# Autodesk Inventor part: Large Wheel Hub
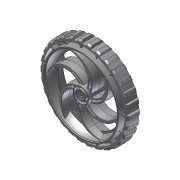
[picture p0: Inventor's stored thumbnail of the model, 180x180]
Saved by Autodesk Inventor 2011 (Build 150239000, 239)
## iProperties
Created: 2010-06
Part Number: Large Wheel Hub
Document SubType Name: Modeling
Designer: kurdi
Density: 1 g/cm^3
Author: kurdi
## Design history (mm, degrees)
workplane "Work Plane1"
sketch "Sketch2"
  geometry: L1 (10.567, 12.411)-(11, 0); L2 (9.792, 12.7)-(10.316, 12.7); L3 (9.314, 9)-(9.433, 12.411); L4 (6.686, 9)-(9.314, 9); L5 (6.567, 12.406)-(6.686, 9); L6 (5.978, 12.7)-(6.262, 12.7); L7 (42.845, 0.75)-(44.637, 0.75); L8 (42.779, 0)-(42.845, 0.75); L9 (57, 8.5)-(57, 0); L10 (55, 8.5)-(57, 8.5); L11 (54.869, 1)-(55, 8.5); L12 (50.838, 1)-(54.869, 1); L13 (50.639, 12.401)-(50.838, 1); L14 (49.42, 12.7)-(50.334, 12.7); L15 (48.362, 11.769)-(49.204, 12.611); L16 (0, 0)-(57, 0); L17 (0, 12.125)-(0, 0); L18 (0, 46.6)-(0, 0); L19 (10.567, -12.411)-(11, 0); L20 (9.792, -12.7)-(10.316, -12.7); L21 (9.314, -9)-(9.433, -12.411); L22 (6.686, -9)-(9.314, -9); L23 (50.838, -1)-(54.869, -1); L24 (54.869, -1)-(55, -8.5); L25 (57, -8.5)-(57, 0); L26 (0, -12.125)-(0, 0); L27 (42.779, 0)-(42.845, -0.75); L28 (42.845, -0.75)-(44.637, -0.75); L29 (48.362, -11.769)-(49.204, -12.611); L30 (49.42, -12.7)-(50.334, -12.7); L31 (50.639, -12.401)-(50.838, -1); L32 (55, -8.5)-(57, -8.5); L33 (5.978, 12.7)-(5.978, 12.446); L34 (5.978, 12.446)-(5.914, 12.446); L35 (5.914, 12.446)-(5.914, 12.7); L36 (5.914, 12.7)-(5.445, 12.7); L37 (5.978, -12.7)-(6.262, -12.7); L38 (5.978, -12.446)-(5.914, -12.446); L39 (5.978, -12.7)-(5.978, -12.446); L40 (5.914, -12.446)-(5.914, -12.7); L41 (5.914, -12.7)-(5.445, -12.7); L42 (6.567, -12.406)-(6.686, -9); A1 r 0.305 centre (10.262, 12.4) between (10.567, 12.411) and (10.316, 12.7); A2 r 0.305 centre (9.738, 12.4) between (9.792, 12.7) and (9.433, 12.411); A3 r 0.305 centre (6.262, 12.395) between (6.567, 12.406) and (6.262, 12.7); A4 r 25.019 centre (0.079, 37.144) between (0, 12.125) and (5.381, 12.693); A5 r 22 centre (26.3, 12.649) between (44.895, 0.892) and (48.274, 11.569); A6 r 0.305 centre (44.637, 1.055) between (44.637, 0.75) and (44.895, 0.892); A7 r 0.305 centre (50.334, 12.395) between (50.639, 12.401) and (50.334, 12.7); A8 r 0.305 centre (49.42, 12.395) between (49.42, 12.7) and (49.204, 12.611); A9 r 0.305 centre (48.578, 11.554) between (48.362, 11.769) and (48.274, 11.569); A10 r 0.305 centre (10.262, -12.4) between (10.316, -12.7) and (10.567, -12.411); A11 r 0.305 centre (9.738, -12.4) between (9.433, -12.411) and (9.792, -12.7); A12 r 0.305 centre (44.637, -1.055) between (44.895, -0.892) and (44.637, -0.75); A13 r 0.305 centre (48.578, -11.554) between (48.274, -11.569) and (48.362, -11.769); A14 r 0.305 centre (49.42, -12.395) between (49.204, -12.611) and (49.42, -12.7); A15 r 22 centre (26.3, -12.649) between (48.274, -11.569) and (44.895, -0.892); A16 r 0.305 centre (50.334, -12.395) between (50.334, -12.7) and (50.639, -12.401); A17 r 0.305 centre (5.445, 12.395) between (5.445, 12.7) and (5.381, 12.693); A18 r 0.305 centre (6.262, -12.395) between (6.262, -12.7) and (6.567, -12.406); A19 r 0.305 centre (5.445, -12.395) between (5.381, -12.693) and (5.445, -12.7); A20 r 25.019 centre (0.079, -37.144) between (5.381, -12.693) and (0, -12.125); 10 further points
  constraints: 86 end point, 44 point on circle, 42 symmetric about line, 20 centre point, 15 tangent, 11 point on line, 5 horizontal, 5 perpendicular, 3 parallel, 2 collinear, 2 vertical, 1 horizontal alignment, 10 other
  dimensions: "d0" = 22 radius of A5; "d14" = 0.3048 radius of A8; "d15" = 0.3048 radius of A7; "d16" = 25.019 radius of A4; "d18" = 0.3048 radius of A2; "d19" = 0.3048 radius of A1; "d21" = 12.4 distance from line of L16 A2.centre; "d24" = 11 distance from line of L1.end L18; "d27" = 2.13091 distance from line of L9 L11.start; "d28" = 4.03112 distance of L12.start L11.start; "d29" = 8.5 distance of L9.start L9.end; "d30" = 2 distance of L10.start L9.start; "d31" = 1 distance between parallel lines of L16 L12; "d32" = 0.3048 radius of A6; "d36" = 2.62857 distance of L4.start L3.start; "d37" = 9 distance between parallel lines of L16 L4; "d38" = 6.68571 distance from line of L17 L4.start; "d42" = 12.64919 distance from line of L16 A5.centre; "d43" = 26.30006 distance from line of L18 A5.centre; "d44" = 0.3048 radius of A9; "d45" = 0.91468 distance of L14.start L14.end; "d46" = 12.7 distance between parallel lines of L16 L14; "d47" = 0.75 distance between parallel lines of L16 L7; "d48" = 0.999943 deg angle of L13 L9; "d49" = 45 deg angle of L9 L15; "d52" = 8.5 distance from line of point (0, 0) L10; "d55" = 38.1 distance from line of L18.start L10; "d60" = 57 distance between parallel lines of L18 L9; "d61" = 57 distance from line of point (0, 0) L9; "d64" = 14.22098 distance from line of L25 L8.start; "d67" = 0.0635 distance of L33.end L34.end; "d69" = 0.254 distance of L6.start L33.end; "d70" = 0.3048 radius of A3; "d71" = 0.3048 radius of A17; "d73" = 51.02237 distance between parallel lines of L33 L9; "d74" = 4.2 distance between parallel lines of L37 L32; "d76" = 51.5546 distance from line of L36.end L9; "d77" = 51.58737 distance from line of point (5.413, 12.7) L9; "d78" = 92 deg angle of L4 L5; "d123" = 92 deg angle of L4 L3; "d130" = 95 deg angle of L16 L8; "d131" = 13.87606 distance from line of point (43.124, 0.75) L9; "d132" = 14.1797 distance from line of point (42.82, 0.472) L9
revolve "Revolution1" sketch "Sketch2" stored, may be unused: angle "d66" = 90 deg
sketch "Sketch3"
  geometry: L1 (1.612, 0.952)-(1.558, 1.007); L2 (1.558, 1.025)-(1.612, 1.079); L3 (1.612, 1.104)-(1.612, 1.079); L4 (1.558, 1.177)-(1.612, 1.231); L5 (1.612, 1.362)-(1.612, 1.231); L6 (1.232, 1.612)-(1.177, 1.558); L7 (1.159, 1.558)-(1.105, 1.612); L8 (1.079, 1.612)-(1.105, 1.612); L9 (1.232, 1.612)-(1.362, 1.612); L10 (1.612, 0.952)-(1.612, -0.952); L11 (1.558, -1.007)-(1.612, -0.952); L12 (1.612, 1.104)-(1.558, 1.159); L13 (1.079, 1.612)-(1.025, 1.558); L14 (-1.362, 1.612)-(-1.231, 1.612); L15 (-1.177, 1.558)-(-1.231, 1.612); L16 (1.007, 1.558)-(0.952, 1.612); L17 (-0.952, 1.613)-(0.952, 1.612); L18 (-0.952, 1.613)-(-1.007, 1.558); L19 (-1.024, 1.558)-(-1.079, 1.612); L20 (-1.104, 1.613)-(-1.079, 1.612); L21 (-1.104, 1.613)-(-1.159, 1.558); L22 (1.613, -1.079)-(1.558, -1.024); L23 (1.613, -1.079)-(1.612, -1.105); L24 (1.558, -1.159)-(1.612, -1.105); L25 (1.613, -1.231)-(1.558, -1.177); L26 (1.613, -1.231)-(1.612, -1.362); L27 (1.362, -1.612)-(1.231, -1.612); L28 (1.177, -1.558)-(1.231, -1.612); L29 (1.104, -1.613)-(1.079, -1.612); L30 (1.024, -1.558)-(1.079, -1.612); L31 (0.952, -1.613)-(1.007, -1.558); L32 (0.952, -1.613)-(-0.952, -1.612); L33 (1.104, -1.613)-(1.159, -1.558); L34 (-1.007, -1.558)-(-0.952, -1.612); L35 (-1.079, -1.612)-(-1.025, -1.558); L36 (-1.079, -1.612)-(-1.105, -1.612); L37 (-1.159, -1.558)-(-1.105, -1.612); L38 (-1.232, -1.612)-(-1.177, -1.558); L39 (-1.612, -0.952)-(-1.558, -1.007); L40 (-1.558, -1.025)-(-1.612, -1.079); L41 (-1.612, -1.104)-(-1.612, -1.079); L42 (-1.612, -1.104)-(-1.558, -1.159); L43 (-1.558, -1.177)-(-1.612, -1.231); L44 (-1.612, -1.362)-(-1.612, -1.231); L45 (-1.232, -1.612)-(-1.362, -1.612); L46 (-1.612, -0.952)-(-1.612, 0.952); L47 (-1.558, 1.007)-(-1.612, 0.952); L48 (-1.613, 1.079)-(-1.558, 1.024); L49 (-1.613, 1.079)-(-1.612, 1.105); L50 (-1.558, 1.159)-(-1.612, 1.105); L51 (-1.613, 1.231)-(-1.558, 1.177); L52 (-1.613, 1.231)-(-1.612, 1.362); A1 r 0.013 centre (1.567, 1.016) between (1.558, 1.025) and (1.558, 1.007); A2 r 0.013 centre (1.567, 1.168) between (1.558, 1.177) and (1.558, 1.159); A3 r 0.25 centre (1.362, 1.362) between (1.612, 1.362) and (1.362, 1.612); A4 r 0.013 centre (1.168, 1.567) between (1.159, 1.558) and (1.177, 1.558); A5 r 0.012 centre (-1.016, 1.566) between (-1.024, 1.558) and (-1.007, 1.558); A6 r 0.012 centre (-1.168, 1.566) between (-1.177, 1.558) and (-1.159, 1.558); A7 r 0.013 centre (1.016, 1.567) between (1.007, 1.558) and (1.025, 1.558); A8 r 0.012 centre (1.566, -1.016) between (1.558, -1.007) and (1.558, -1.024); A9 r 0.013 centre (1.567, -1.168) between (1.558, -1.159) and (1.558, -1.177); A10 r 0.25 centre (1.362, -1.362) between (1.362, -1.612) and (1.612, -1.362); A11 r 0.012 centre (1.168, -1.566) between (1.177, -1.558) and (1.159, -1.558); A12 r 0.012 centre (1.016, -1.566) between (1.024, -1.558) and (1.007, -1.558); A13 r 0.013 centre (-1.016, -1.567) between (-1.007, -1.558) and (-1.025, -1.558); A14 r 0.013 centre (-1.168, -1.567) between (-1.159, -1.558) and (-1.177, -1.558); A15 r 0.013 centre (-1.567, -1.168) between (-1.558, -1.177) and (-1.558, -1.159); A16 r 0.013 centre (-1.567, -1.016) between (-1.558, -1.025) and (-1.558, -1.007); A17 r 0.25 centre (-1.362, -1.362) between (-1.612, -1.362) and (-1.362, -1.612); A18 r 0.25 centre (-1.362, 1.362) between (-1.362, 1.612) and (-1.612, 1.362); A19 r 0.013 centre (-1.567, 1.168) between (-1.558, 1.159) and (-1.558, 1.177); A20 r 0.012 centre (-1.566, 1.016) between (-1.558, 1.007) and (-1.558, 1.024); 1 further point
  constraints: 104 end point, 40 point on circle, 20 centre point
feature "iFeature1:1" sketch "Sketch3"
sketch "Sketch4"
  geometry: A1 r 26.527 centre (-14.987, 15.537) between (9.122, 4.473) and (-1.422, 38.333); A2 r 35.155 centre (-19.399, 8.122) between (-1.422, 38.333) and (-22.795, 43.113); A3 r 22.463 centre (-16.436, 17.645) between (4.368, 9.173) and (-5.564, 37.302); A4 r 37.313 centre (-23.624, 4.651) between (-5.564, 37.302) and (-24.882, 41.943); A5 r 24.749 centre (-14.987, 15.537) between (7.972, 6.298) and (8.602, 23.024); A6 r 24.241 centre (-16.436, 17.645) between (5.914, 8.261) and (7.277, 22.675); A7 r 0.686 centre (7.948, 22.817) between (8.602, 23.024) and (7.277, 22.675); A8 r 10.16 centre (0, 0) between (5.914, 8.261) and (4.368, 9.173); A9 r 10.16 centre (0, 0) between (9.122, 4.473) and (7.972, 6.298); A10 r 48.768 centre (0, 0) between (-22.795, 43.113) and (-24.882, 41.943); A11 r 10.16 centre (0, 0) between (7.972, 6.298) and (5.914, 8.261); 2 further points
  constraints: 22 point on circle, 11 centre point, 4 tangent, 3 coincident, 1 concentric
  dimensions: "d79" = 0.6858 radius of A7; "d85" = 26.52672 radius of A1; "d86" = 35.15477 radius of A2; "d87" = 37.31272 radius of A4; "d88" = 22.46313 radius of A3; "d89" = 48.768 radius of A10; "d90" = 1.778 radial gap between concentric circles of A1 A5; "d91" = 1.778 radial gap between concentric circles of A3 A6; "d92" = 10.16 radius of A9; "d93" = 10.16 radius of A8; "d103" = 16.43647 horizontal distance of A3.centre point (0, 0); "d104" = 19.39935 horizontal distance of A2.centre point (0, 0); "d105" = 23.62407 horizontal distance of A4.centre point (0, 0); "d106" = 4.65123 vertical distance of A4.centre point (0, 0); "d107" = 8.12226 vertical distance of point (0, 0) A2.centre; "d108" = 14.98711 horizontal distance of point (0, 0) A1.centre
extrude "Extrusion1" join sketch "Sketch4" distance "d110" = 8.9916; taper "d111" = 4 deg
extrude "Extrusion2" cut sketch "Sketch4" distance "d112" = 8.255; taper "d113" = -2 deg
sketch "Sketch6"
  geometry: C1 r 9.314 at (0, 0) reference; C2 r 6.686 at (0, 0) reference; A1 r 24.241 centre (-16.436, 17.645) between (6.118, 8.761) and (7.277, 22.675); A2 r 24.749 centre (-14.987, 15.537) between (8.192, 6.862) and (8.602, 23.024); A3 r 9.314 centre (0, 0) between (5.565, 7.469) and (7.59, 5.399); A4 r 6.686 centre (0, 0) between (4.312, 5.11) and (6.14, 2.646); A5 r 24.241 centre (-16.436, 17.645) between (4.312, 5.11) and (5.565, 7.469); A6 r 24.749 centre (-14.987, 15.537) between (6.14, 2.646) and (7.59, 5.399); A7 r 6.686 centre (0, 0) between (6.14, 2.646) and (4.312, 5.11); A8 r 9.314 centre (0, 0) between (7.59, 5.399) and (5.565, 7.469)
  constraints: 16 point on circle, 8 centre point, 6 concentric
extrude "Extrusion4" cut sketch "Sketch6" distance "d116" = 8.255; taper "d117" = -2 deg; dims "d118" = 2.54, "d119" = -2 deg
fillet "Fillet1" dims "d121" = 0.381
mirror "Mirror1"
sketch "Sketch7"
  geometry: L1 (3.523, 42.634)-(3.523, 43.142); L2 (1.43, 37.168)-(0.993, 36.908); A1 r 35.784 centre (-19.399, 8.122) between (-1.1, 38.873) and (-7.967, 42.031) reference; A2 r 42.779 centre (0, 0) between (-14.604, 40.209) and (-7.967, 42.031) reference; A3 r 42.779 centre (0, 0) between (3.523, 42.634) and (-7.967, 42.031); A4 r 3.048 centre (3.272, 39.596) between (3.523, 42.634) and (1.43, 37.168); A5 r 43.285 centre (0, 0) between (3.523, 43.142) and (-9.981, 42.119); A6 r 35.277 centre (-19.399, 8.122) between (0.993, 36.908) and (-9.981, 42.119); A7 r 27.155 centre (-14.987, 15.537) between (9.928, 4.736) and (-1.1, 38.873) reference; 1 further point
  constraints: 11 point on circle, 4 centre point, 4 end point, 3 concentric, 2 tangent, 1 vertical
  dimensions: "d133" = 3.048 radius of A4; "d134" = 0.508 distance of L1.start L1.end; "d135" = 0.508 distance of L2.start L2.end
extrude "Extrusion5" join sketch "Sketch7" stored distance "d136" = 1.4986; taper "d137" = -4 deg
pattern_circular "Circular Pattern1" dims "d125" = 360 deg
sketch "Sketch8"
  geometry: L1 (-57, 8.5)-(57, 8.5) reference; L2 (-50.639, 12.401)-(-50.838, 1) reference; L3 (-54.869, 1)-(54.869, 1) reference; L4 (-50.838, 1)-(50.838, 1) reference; L5 (-50.725, 7.459)-(-53.519, 7.459); L6 (-53.519, 7.459)-(-53.519, 7.992); L7 (-54.027, 8.5)-(-55.805, 8.5); A1 r 0.508 centre (-54.027, 7.992) between (-53.519, 7.992) and (-54.027, 8.5); 1 further point
  constraints: 6 end point, 3 point on line, 2 point on circle, 2 tangent, 1 centre point, 1 parallel, 1 perpendicular
  dimensions: "d138" = 2.794 distance of L5.start L5.end; "d139" = 0.508 radius of A1; "d140" = 0.5334 distance of L5.end L6.end; "d141" = 5.08 horizontal distance of L7.end L5.start
feature "Rib1" sketch "Sketch8" dims "d142" = 2.54, "d143" = 1.27, "d144" = 0
mirror "Mirror2"
pattern_circular "Circular Pattern2" dims angle "d146" = 360 deg
sketch "Sketch9"
  geometry: L1 (0, 0)-(59.995, 0); L2 (59.951, 2.286)-(56.919, 3.042); L3 (59.951, -2.286)-(56.919, -3.042); A1 r 57 centre (0, 0) between (56.919, 3.042) and (56.919, -3.042) reference; A2 r 59.995 centre (0, 0) between (59.951, -2.286) and (59.951, 2.286); A3 r 57 centre (0, 0) between (56.919, -3.042) and (56.919, 3.042); 1 further point
  constraints: 8 point on circle, 7 end point, 2 centre point, 1 coincident, 1 concentric, 1 horizontal
  dimensions: "d148" = 14 deg angle of L1 L2; "d149" = 14 deg angle of L1 L3; "d150" = 59.9948 radius of A2; "d151" = 4.572 distance of L3.start L2.start
extrude "Extrusion6" join sketch "Sketch9" stored distance "d152" = 1.4986; taper "d153" = 0 deg
sketch "Sketch10"
  geometry: L1 (-59.951, 8.5)-(-56.919, 8.5) reference; L2 (-59.951, -8.5)-(-59.951, 8.5) reference; L3 (-56.919, 8.5)-(-57.808, 8.5); L4 (-59.951, 0)-(-59.951, 5.715); L5 (-57.808, 8.5)-(-57.808, 9.063); L6 (-57.808, 9.063)-(-60.666, 9.063); L7 (-60.666, 9.063)-(-60.666, 5.715); L8 (-60.666, 5.715)-(-59.951, 5.715); L9 (0, 17.787)-(0, -17.787) reference; A1 r 3.81 centre (-56.2, 5.046) between (-57.808, 8.5) and (-59.951, 5.715); 2 further points
  constraints: 12 end point, 3 parallel, 3 perpendicular, 2 coincident, 2 collinear, 2 point on circle, 1 centre point, 1 midpoint
  dimensions: "d154" = 0.889 distance of L3.start L3.end; "d155" = 5.715 distance of L4.start L4.end; "d156" = 3.81 radius of A1; "d157" = 0.5632 distance of L3.end L5.end; "d158" = 0.71516 distance of L7.end L4.end
workaxis "Work Axis1"
revolve "Revolution2" stored, may be unused: angle "d159" = 90 deg
mirror "Mirror3"
fillet "Fillet3" dims "d163" = 0.3048
body "Solid1"
pattern_circular "Circular Pattern3" dims "d161" = 360 deg
node "Projected Loop1"
other parameters: "d3" = 57, "d4" = 26.30006, "d6" = 42.77864, "d7" = 55, "d11" = 11, "d80" = 21.844, "d109" = 8.9916
